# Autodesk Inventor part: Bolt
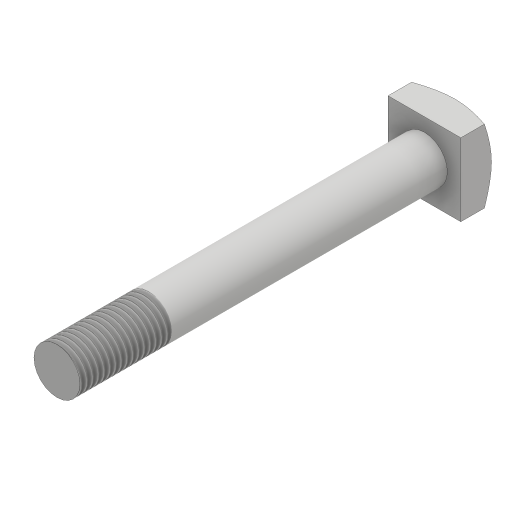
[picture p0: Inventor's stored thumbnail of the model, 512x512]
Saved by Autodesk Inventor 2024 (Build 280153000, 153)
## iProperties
Created: 2016-05
Part Number: Bolt
Material: Generic
Document SubType Name: Modeling
Designer: CADCIM
Density: 1 g/cm^3
Appearance: Default
Author: CADCIM
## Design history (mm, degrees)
sketch "Sketch1"
  geometry: L1 (9.5, 9.5)-(-9.5, 9.5); L2 (-9.5, 9.5)-(-9.5, -9.5); L3 (-9.5, -9.5)-(9.5, -9.5); L4 (9.5, -9.5)-(9.5, 9.5); L5 (0, 0)-(0, 14.108); L6 (0, 0)-(-17.802, 0)
  constraints: 12 end point, 2 horizontal, 2 parallel, 2 perpendicular, 1 vertical, 2 other
  dimensions: "d0" = 19 distance of L3.end L1.start
extrude "Extrusion1" new body sketch "Sketch1" distance "d1" = 8; taper "d2" = 0 deg
sketch "Sketch3"
  geometry: L1 (9.5, 9.5)-(-9.5, 9.5) reference; C1 r 9.5 at (0, 0); 1 further point
  constraints: 1 centre point, 1 coincident, 1 tangent
extrude "Extrusion3" sketch "Sketch3" distance "d6" = 96; taper "d7" = 65 deg
sketch "Sketch4"
  geometry: C1 r 6 at (0, 0); 1 further point
  constraints: 1 centre point, 1 coincident
  dimensions: "d10" = 12 diameter of C1
extrude "Extrusion4" join sketch "Sketch4" distance "d11" = 96; taper "d12" = 0 deg
thread "Thread2" dims "d13" = 24, "d14" = 0
body "Solid1"
